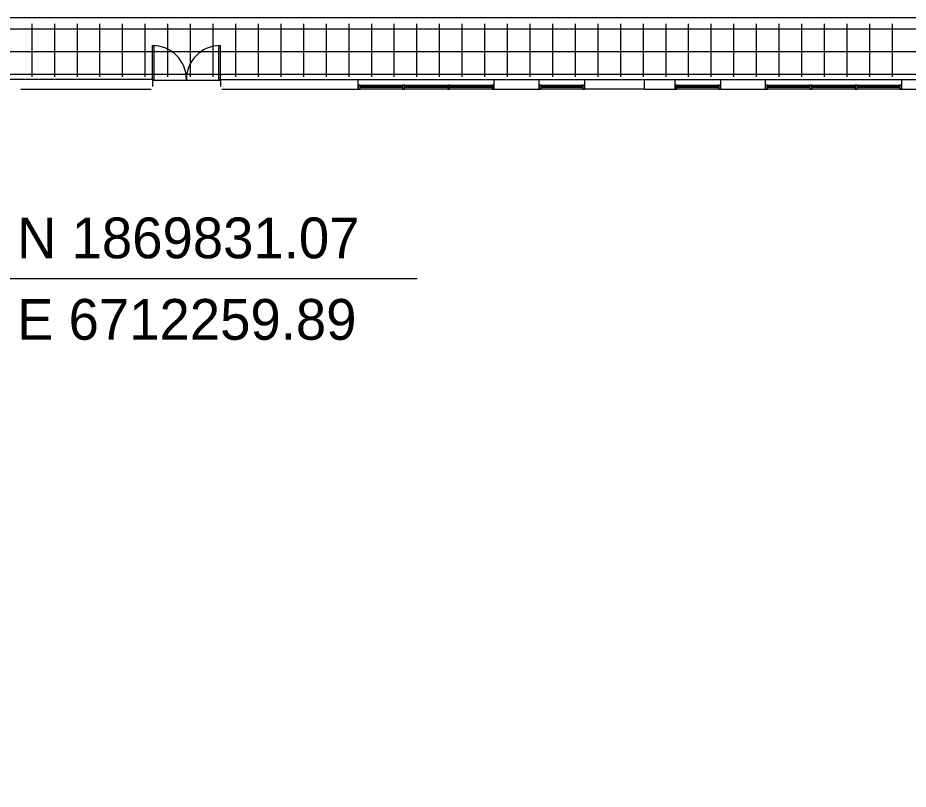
# Model space of a CAD drawing. Extents: x 6712138 to 6712574, y 1869536 to 1870160.
# Drawn here: x 6712277.8 to 6712356.5, y 1869768.1 to 1869836.3 of the extents above; entities that cross this region are included whole.
import ezdxf

# ---------------------------------------------------------------- set-up
doc = ezdxf.new("R2010")
doc.units = 0
for name, color, linetype in [('A-DETL-MBND', 7, 'Continuous'), ('A-FLOR-OTLN', 7, 'Continuous'), ('A-FLOR-PATT', 7, 'Continuous'), ('A-GLAZ', 7, 'Continuous'), ('A-GLAZ-FRAM', 7, 'Continuous'), ('A-WALL-FULL-EXT', 7, 'Continuous'), ('I-WALL', 7, 'Continuous')]:
    doc.layers.add(name, color=color, linetype=linetype)

msp = doc.modelspace()

# ---------------------------------------------------------------- linework, layer by layer
at = {"layer": 'A-DETL-MBND'}
for p, q in [((6712289.745, 1869833.833), (6712289.891, 1869833.833)), ((6712289.745, 1869830.833), (6712289.745, 1869833.833)), ((6712289.891, 1869830.833), (6712289.891, 1869833.833)), ((6712295.599, 1869830.833), (6712295.599, 1869833.83)), ((6712295.745, 1869830.833), (6712295.745, 1869833.833)), ((6712289.745, 1869830.833), (6712289.891, 1869830.833)), ((6712295.745, 1869830.833), (6712295.599, 1869830.833))]:
    msp.add_line(p, q, dxfattribs=at)
for centre, start, end in [((6712289.745, 1869830.833), 0, 90), ((6712295.745, 1869830.833), 90, 180)]:
    msp.add_arc(centre, 3, start, end, dxfattribs=at)
at = {"layer": 'A-FLOR-OTLN'}
msp.add_line((6712289.724, 1869830.76), (6712295.724, 1869830.76), dxfattribs=at)
msp.add_lwpolyline([(6712463.745, 1869723.291), (6712465.141, 1869723.291), (6712465.141, 1869836.281), (6712254.683, 1869836.281)], dxfattribs=at)
at = {"layer": 'A-FLOR-PATT'}
for p, q in [((6712279.11, 1869831.073), (6712279.11, 1869835.76)), ((6712281.11, 1869831.073), (6712281.11, 1869835.76)), ((6712283.11, 1869831.073), (6712283.11, 1869835.76)), ((6712285.11, 1869831.073), (6712285.11, 1869835.76)), ((6712287.11, 1869831.073), (6712287.11, 1869835.76)), ((6712289.11, 1869831.073), (6712289.11, 1869835.76)), ((6712291.11, 1869831.073), (6712291.11, 1869835.76)), ((6712293.11, 1869831.073), (6712293.11, 1869835.76)), ((6712295.11, 1869831.073), (6712295.11, 1869835.76)), ((6712297.11, 1869831.073), (6712297.11, 1869835.76)), ((6712299.11, 1869831.073), (6712299.11, 1869835.76)), ((6712301.11, 1869831.073), (6712301.11, 1869835.76)), ((6712303.11, 1869831.073), (6712303.11, 1869835.76)), ((6712305.11, 1869831.073), (6712305.11, 1869835.76)), ((6712307.11, 1869831.073), (6712307.11, 1869835.76)), ((6712309.11, 1869831.073), (6712309.11, 1869835.76)), ((6712311.11, 1869831.073), (6712311.11, 1869835.76)), ((6712313.11, 1869831.073), (6712313.11, 1869835.76)), ((6712315.11, 1869831.073), (6712315.11, 1869835.76)), ((6712317.11, 1869831.073), (6712317.11, 1869835.76)), ((6712319.11, 1869831.073), (6712319.11, 1869835.76)), ((6712321.11, 1869831.073), (6712321.11, 1869835.76)), ((6712323.11, 1869831.073), (6712323.11, 1869835.76)), ((6712325.11, 1869831.073), (6712325.11, 1869835.76)), ((6712327.11, 1869831.073), (6712327.11, 1869835.76)), ((6712329.11, 1869831.073), (6712329.11, 1869835.76)), ((6712331.11, 1869831.073), (6712331.11, 1869835.76)), ((6712333.11, 1869831.073), (6712333.11, 1869835.76)), ((6712335.11, 1869831.073), (6712335.11, 1869835.76)), ((6712337.11, 1869831.073), (6712337.11, 1869835.76)), ((6712339.11, 1869831.073), (6712339.11, 1869835.76)), ((6712341.11, 1869831.073), (6712341.11, 1869835.76)), ((6712343.11, 1869831.073), (6712343.11, 1869835.76)), ((6712345.11, 1869831.073), (6712345.11, 1869835.76)), ((6712347.11, 1869831.073), (6712347.11, 1869835.76)), ((6712349.11, 1869831.073), (6712349.11, 1869835.76)), ((6712351.11, 1869831.073), (6712351.11, 1869835.76)), ((6712353.11, 1869831.073), (6712353.11, 1869835.76)), ((6712355.11, 1869831.073), (6712355.11, 1869835.76)), ((6712464.62, 1869835.281), (6712255.204, 1869835.281)), ((6712464.62, 1869833.281), (6712255.204, 1869833.281)), ((6712464.619, 1869831.281), (6712255.204, 1869831.281))]:
    msp.add_line(p, q, dxfattribs=at)
at = {"layer": 'A-GLAZ'}
for p, q in [((6712311.829, 1869830.219), (6712308.079, 1869830.219)), ((6712308.079, 1869830.219), (6712308.079, 1869830.156)), ((6712308.079, 1869830.156), (6712311.829, 1869830.156)), ((6712311.829, 1869830.156), (6712311.829, 1869830.219)), ((6712315.829, 1869830.219), (6712311.995, 1869830.219)), ((6712311.995, 1869830.219), (6712311.995, 1869830.156)), ((6712311.995, 1869830.156), (6712315.829, 1869830.156)), ((6712315.829, 1869830.156), (6712315.829, 1869830.219)), ((6712319.745, 1869830.219), (6712315.995, 1869830.219)), ((6712315.995, 1869830.219), (6712315.995, 1869830.156)), ((6712315.995, 1869830.156), (6712319.745, 1869830.156)), ((6712319.745, 1869830.156), (6712319.745, 1869830.219)), ((6712324.079, 1869830.219), (6712324.079, 1869830.156)), ((6712327.745, 1869830.219), (6712324.079, 1869830.219)), ((6712324.079, 1869830.156), (6712327.745, 1869830.156)), ((6712327.745, 1869830.156), (6712327.745, 1869830.219)), ((6712336.079, 1869830.219), (6712336.079, 1869830.156)), ((6712339.745, 1869830.219), (6712336.079, 1869830.219)), ((6712336.079, 1869830.156), (6712339.745, 1869830.156)), ((6712339.745, 1869830.156), (6712339.745, 1869830.219)), ((6712347.829, 1869830.219), (6712344.079, 1869830.219)), ((6712344.079, 1869830.219), (6712344.079, 1869830.156)), ((6712344.079, 1869830.156), (6712347.829, 1869830.156)), ((6712347.829, 1869830.156), (6712347.829, 1869830.219)), ((6712351.829, 1869830.219), (6712347.995, 1869830.219)), ((6712347.995, 1869830.219), (6712347.995, 1869830.156)), ((6712347.995, 1869830.156), (6712351.829, 1869830.156)), ((6712351.829, 1869830.156), (6712351.829, 1869830.219)), ((6712355.745, 1869830.219), (6712351.995, 1869830.219)), ((6712351.995, 1869830.219), (6712351.995, 1869830.156)), ((6712351.995, 1869830.156), (6712355.745, 1869830.156)), ((6712355.745, 1869830.156), (6712355.745, 1869830.219))]:
    msp.add_line(p, q, dxfattribs=at)
at = {"layer": 'A-GLAZ-FRAM'}
for p, q in [((6712308.079, 1869830.323), (6712307.912, 1869830.323)), ((6712307.912, 1869830.323), (6712307.912, 1869829.989)), ((6712307.912, 1869829.989), (6712308.079, 1869829.989)), ((6712308.079, 1869829.989), (6712308.079, 1869830.323)), ((6712308.079, 1869830.323), (6712311.829, 1869830.323)), ((6712311.829, 1869829.989), (6712308.079, 1869829.989)), ((6712311.995, 1869830.323), (6712311.829, 1869830.323)), ((6712311.829, 1869830.323), (6712311.829, 1869829.989)), ((6712311.829, 1869829.989), (6712311.995, 1869829.989)), ((6712311.995, 1869829.989), (6712311.995, 1869830.323)), ((6712311.995, 1869830.323), (6712315.829, 1869830.323)), ((6712315.829, 1869829.989), (6712311.995, 1869829.989)), ((6712315.995, 1869830.323), (6712315.829, 1869830.323)), ((6712315.829, 1869830.323), (6712315.829, 1869829.989)), ((6712315.829, 1869829.989), (6712315.995, 1869829.989)), ((6712315.995, 1869829.989), (6712315.995, 1869830.323)), ((6712315.995, 1869830.323), (6712319.745, 1869830.323)), ((6712319.745, 1869829.989), (6712315.995, 1869829.989)), ((6712319.912, 1869830.323), (6712319.745, 1869830.323)), ((6712319.745, 1869830.323), (6712319.745, 1869829.989)), ((6712319.745, 1869829.989), (6712319.912, 1869829.989)), ((6712319.912, 1869829.989), (6712319.912, 1869830.323)), ((6712323.912, 1869830.323), (6712323.912, 1869829.989)), ((6712324.079, 1869830.323), (6712323.912, 1869830.323)), ((6712323.912, 1869829.989), (6712324.079, 1869829.989)), ((6712324.079, 1869829.989), (6712324.079, 1869830.323)), ((6712324.079, 1869830.323), (6712327.745, 1869830.323)), ((6712327.745, 1869829.989), (6712324.079, 1869829.989)), ((6712327.745, 1869830.323), (6712327.745, 1869829.989)), ((6712327.912, 1869830.323), (6712327.745, 1869830.323)), ((6712327.745, 1869829.989), (6712327.912, 1869829.989)), ((6712327.912, 1869829.989), (6712327.912, 1869830.323)), ((6712335.912, 1869830.323), (6712335.912, 1869829.989)), ((6712336.079, 1869830.323), (6712335.912, 1869830.323)), ((6712335.912, 1869829.989), (6712336.079, 1869829.989)), ((6712336.079, 1869829.989), (6712336.079, 1869830.323)), ((6712336.079, 1869830.323), (6712339.745, 1869830.323)), ((6712339.745, 1869829.989), (6712336.079, 1869829.989)), ((6712339.745, 1869830.323), (6712339.745, 1869829.989)), ((6712339.912, 1869830.323), (6712339.745, 1869830.323)), ((6712339.745, 1869829.989), (6712339.912, 1869829.989)), ((6712339.912, 1869829.989), (6712339.912, 1869830.323)), ((6712344.079, 1869830.323), (6712343.912, 1869830.323)), ((6712343.912, 1869830.323), (6712343.912, 1869829.989)), ((6712343.912, 1869829.989), (6712344.079, 1869829.989)), ((6712344.079, 1869829.989), (6712344.079, 1869830.323)), ((6712344.079, 1869830.323), (6712347.829, 1869830.323)), ((6712347.829, 1869829.989), (6712344.079, 1869829.989)), ((6712347.995, 1869830.323), (6712347.829, 1869830.323)), ((6712347.829, 1869830.323), (6712347.829, 1869829.989)), ((6712347.829, 1869829.989), (6712347.995, 1869829.989)), ((6712347.995, 1869829.989), (6712347.995, 1869830.323)), ((6712347.995, 1869830.323), (6712351.829, 1869830.323)), ((6712351.829, 1869829.989), (6712347.995, 1869829.989)), ((6712351.995, 1869830.323), (6712351.829, 1869830.323)), ((6712351.829, 1869830.323), (6712351.829, 1869829.989)), ((6712351.829, 1869829.989), (6712351.995, 1869829.989)), ((6712351.995, 1869829.989), (6712351.995, 1869830.323)), ((6712351.995, 1869830.323), (6712355.745, 1869830.323)), ((6712355.745, 1869829.989), (6712351.995, 1869829.989)), ((6712355.912, 1869830.323), (6712355.745, 1869830.323)), ((6712355.745, 1869830.323), (6712355.745, 1869829.989)), ((6712355.745, 1869829.989), (6712355.912, 1869829.989)), ((6712355.912, 1869829.989), (6712355.912, 1869830.323))]:
    msp.add_line(p, q, dxfattribs=at)
at = {"layer": 'A-WALL-FULL-EXT'}
for p, q in [((6712289.784, 1869830.834), (6712270.079, 1869830.833)), ((6712289.745, 1869830.833), (6712289.745, 1869830.203)), ((6712295.745, 1869830.833), (6712295.745, 1869830.203)), ((6712295.745, 1869830.833), (6712421.652, 1869830.833)), ((6712307.912, 1869829.989), (6712307.912, 1869830.833)), ((6712319.912, 1869830.833), (6712319.912, 1869829.989)), ((6712323.912, 1869829.989), (6712323.912, 1869830.833)), ((6712327.912, 1869830.833), (6712327.912, 1869829.989)), ((6712333.214, 1869829.989), (6712333.214, 1869830.833)), ((6712335.912, 1869829.989), (6712335.912, 1869830.833)), ((6712339.912, 1869830.833), (6712339.912, 1869829.989)), ((6712343.912, 1869829.989), (6712343.912, 1869830.833)), ((6712355.912, 1869830.833), (6712355.912, 1869829.989)), ((6712278.12, 1869829.989), (6712289.62, 1869829.989)), ((6712295.87, 1869829.989), (6712302.088, 1869829.989)), ((6712302.088, 1869829.989), (6712302.63, 1869829.989)), ((6712302.63, 1869829.989), (6712307.912, 1869829.989)), ((6712319.912, 1869829.989), (6712323.912, 1869829.989)), ((6712333.214, 1869829.989), (6712327.912, 1869829.989)), ((6712333.214, 1869829.989), (6712335.912, 1869829.989)), ((6712339.912, 1869829.989), (6712343.912, 1869829.989)), ((6712355.912, 1869829.989), (6712359.912, 1869829.989))]:
    msp.add_line(p, q, dxfattribs=at)
at = {"layer": 'I-WALL'}
msp.add_lwpolyline([(6712272.387, 1869813.232), (6712313.135, 1869813.232)], dxfattribs=at)

# ---------------------------------------------------------------- texts
for s, p in [('N 1869831.07', (6712277.787, 1869815.032)), ('E 6712259.89', (6712277.787, 1869807.832))]:
    msp.add_text(s, height=3.6, dxfattribs=at).set_placement(p)

doc.saveas('drawing.dxf')
